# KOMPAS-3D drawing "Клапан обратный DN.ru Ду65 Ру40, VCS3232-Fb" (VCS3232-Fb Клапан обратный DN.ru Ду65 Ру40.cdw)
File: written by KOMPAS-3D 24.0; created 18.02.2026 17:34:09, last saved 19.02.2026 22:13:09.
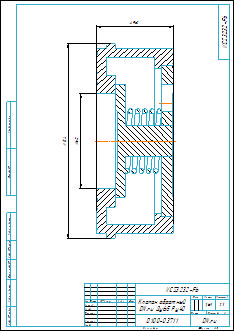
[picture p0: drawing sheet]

Document properties: v313: 1; D: 58; d: 20; a: 1; L: 28; Артикул: D100-03711; Автор: R2D2; Форматы листов документа: A3; Полное имя файла: VCS3232-Fb Клапан обратный DN.ru Ду65 Ру40.m3d; Масса: 1.61; Наименование: Клапан обратный DN.ru Ду65 Ру40; Количество листов документа: 1; Примечание: D100-03711

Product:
- Body: Тело 1  | qty 1
    Масса: 1.439922
- Body: Тело 2  | qty 1
    Масса: 0.57553
- Part/product: Клапан обратный DN.ru Ду65 Ру40  | designation VCS3232-Fb
    Масса: 1.61
    Примечание: D100-03711
    additional columns: 1; D100-03711

Views: Вид 1, Местный разрез 1, Справа
Referenced files in E:\Работа\Зайцев\VCS3232-Fb Клапан обратный DN.ru Ду15-100\DN32\: VCS3232-Fb Клапан обратный DN.ru Ду32 Ру40.m3d
Referenced files in E:\Работа\Зайцев\VCS3232-Fb Клапан обратный DN.ru Ду15-100\DN25\: VCS3232-Fb Клапан обратный DN.ru Ду25 Ру40.m3d
Referenced files in E:\Работа\Зайцев\VCS3232-Fb Клапан обратный DN.ru Ду15-100\DN65\: VCS3232-Fb Клапан обратный DN.ru Ду65 Ру40.m3d
Referenced files in E:\Работа\Зайцев\Для компаса\: чертеж DN.ru.cdt
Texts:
  VCS3232-Fb
  чертеж DN.ru.cdt
  Клапан обратный
  DN.ru Ду65 Ру40
  prop
  Клапан обратный DN.ru Ду65 Ру40
  VCS3232-Fb Клапан обратный DN.ru Ду65 Ру40
Dimensions and other numbers on the sheet: 0; 3; 2; 4; 60; 124; 49±2; 6; 2:1; 1; 1,61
